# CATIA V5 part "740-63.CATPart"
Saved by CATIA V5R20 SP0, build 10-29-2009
Part number: 740-63
Bounding box of the stored display mesh (mm): x -47.4 to 47.4, y -44.5 to 47.4, z -60 to 20
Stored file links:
  C:\Users\Utente\Desktop\IO LAVORO\3D X SITO CF\X SITO\740\740-63.CATPart
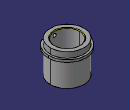
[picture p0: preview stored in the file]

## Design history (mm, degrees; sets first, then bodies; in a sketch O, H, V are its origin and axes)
Set1
  DatumSurface1 to DatumSurface35 "740-63"
Body1 (main body)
